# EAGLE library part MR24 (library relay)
RELAY 4 x switch
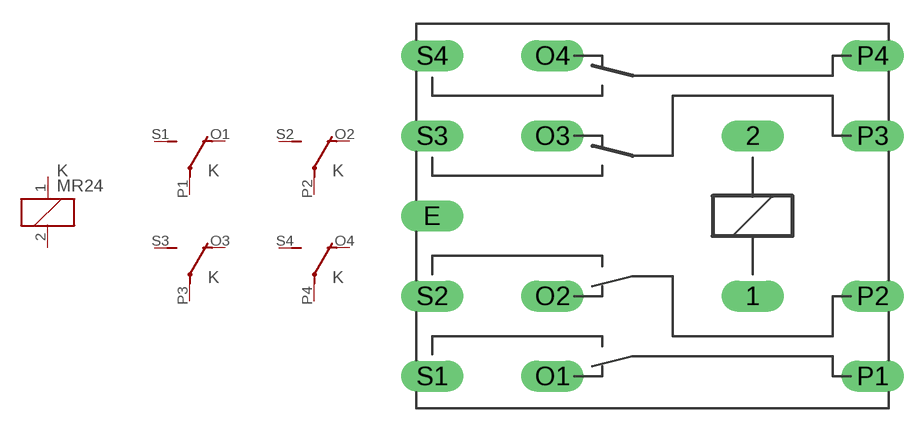
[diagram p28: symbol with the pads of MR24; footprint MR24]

Designator prefix K; gates 1=K 2=U 3=U 4=U 5=U

## MR24 (OC_FARNELL: unknown; OC_NEWARK: unknown)  [MR24]
1  1:1  pas
2  1:2  pas
O1  2:O  pas
O2  3:O  pas
O3  4:O  pas
O4  5:O  pas
P1  2:P  pas
P2  3:P  pas
P3  4:P  pas
P4  5:P  pas
S1  2:S  pas
S2  3:S  pas
S3  4:S  pas
S4  5:S  pas

## Footprint MR24 (pad centres in mm)
RELAY 4 x switch
drill 1.321 long: 1 15.24,-5.08; 2 15.24,5.08; E -5.08,0; O1 2.54,-10.16; O2 2.54,-5.08; O3 2.54,5.08; O4 2.54,10.16; P1 22.86,-10.16; P2 22.86,-5.08; P3 22.86,5.08; P4 22.86,10.16; S1 -5.08,-10.16; S2 -5.08,-5.08; S3 -5.08,5.08; S4 -5.08,10.16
